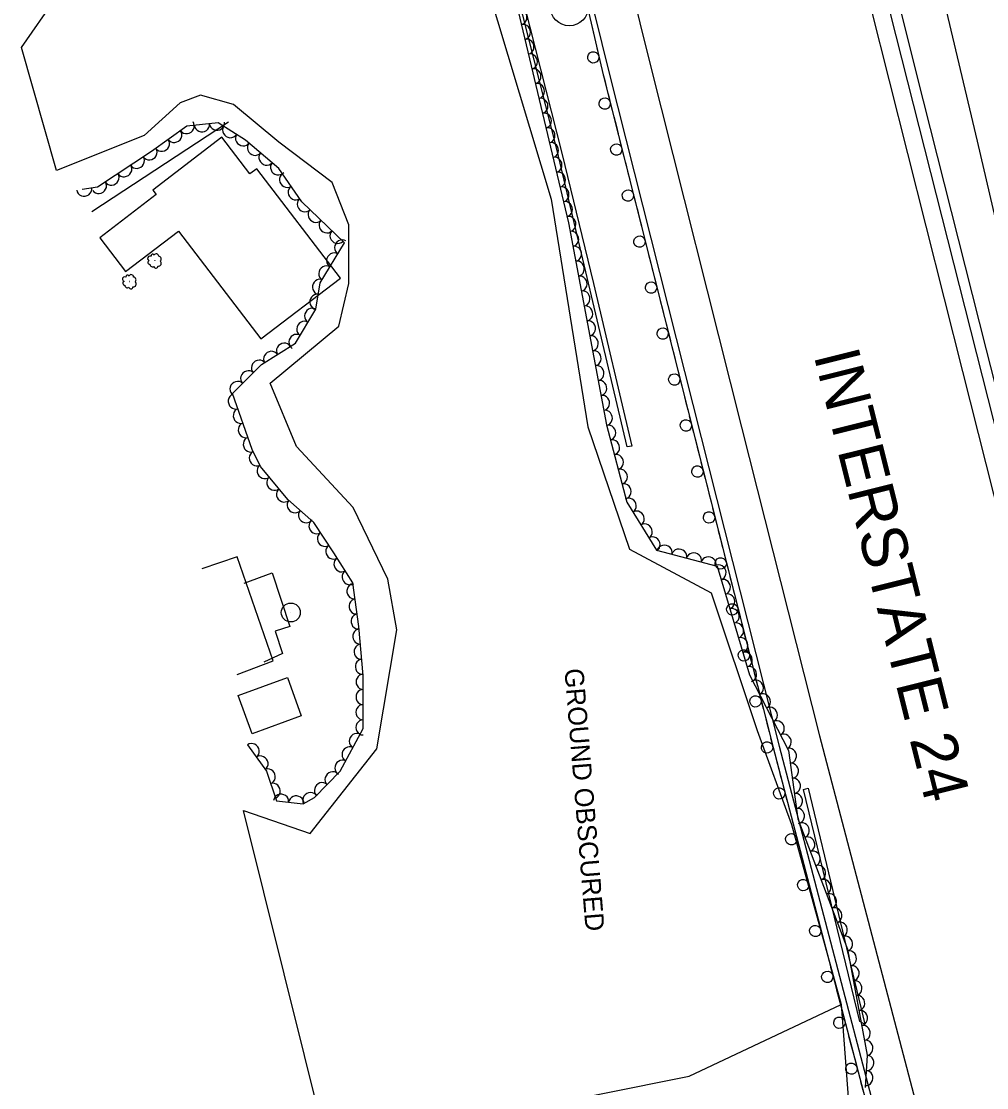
# Model space of a CAD drawing. Extents: x 1746719 to 1766531, y 631721 to 662391.
# Drawn here: x 1753677.7 to 1753932, y 651183.8 to 651464.9 of the extents above; entities that cross this region are included whole.
import ezdxf

# ---------------------------------------------------------------- set-up
doc = ezdxf.new("R2010")
doc.units = 0
for name, color, linetype in [('SURVEY - AERIAL SURVEY - Photo Control - Points - Elevations', 7, 'Continuous'), ('SURVEY - AERIAL SURVEY - Photo Control - Points - Locators', 7, 'Continuous'), ('SURVEY - AERIAL SURVEY - Photo Control - Points - Numbers', 7, 'Continuous'), ('SURVEY - AERIAL SURVEY - Photo Control with Text', 7, 'Continuous'), ('SURVEY - CENTERLINE - Existing Roads Curve Text', 7, 'Continuous'), ('SURVEY - CONTROL - Grid', 7, 'Continuous'), ('SURVEY - CONTROL - Points - Numbers', 7, 'Continuous')]:
    doc.layers.add(name, color=color, linetype=linetype)

msp = doc.modelspace()

# ---------------------------------------------------------------- linework, layer by layer
at = {"layer": 'SURVEY - AERIAL SURVEY - Photo Control - Points - Elevations'}
for points in [[(1753816.84, 651890.61), (1753830.85, 651831.07), (1753849.61, 651754.68), (1753866.95, 651686.19), (1753887.01, 651606.61), (1753909.25, 651518.98), (1753929.48, 651433.33), (1753948.74, 651350.66), (1753973.86, 651243.1), (1753985.66, 651193.84)], [(1753794.98, 651884.53), (1753806.82, 651840.15), (1753821.01, 651784.89), (1753834.83, 651732.27), (1753860.34, 651631.97), (1753880.16, 651554.64), (1753901.48, 651468.39), (1753925.64, 651372.59), (1753946.08, 651291.56), (1753972.17, 651192.06)], [(1753733.96, 651866.94), (1753776.74, 651717.25), (1753802.2, 651617.13), (1753821.97, 651539.99), (1753843.26, 651453.86), (1753867.46, 651357.92), (1753887.97, 651276.61), (1753914.13, 651176.84)], [(1753723.39, 651863.92), (1753766.12, 651714.38), (1753791.54, 651614.41), (1753811.31, 651537.31), (1753832.59, 651451.19), (1753856.8, 651355.23), (1753877.32, 651273.87), (1753903.49, 651174.05)]]:
    msp.add_lwpolyline(points, dxfattribs=at)
at = {"layer": 'SURVEY - AERIAL SURVEY - Photo Control - Points - Locators'}
for points in [[(1753736.22, 651256.87), (1753753.86, 651250.84), (1753771.37, 651273.18), (1753776.68, 651304.52), (1753774.32, 651317.9), (1753765.17, 651336.78), (1753750.18, 651352.85), (1753743.25, 651369.51), (1753761.37, 651384.52), (1753763.97, 651395.81), (1753763.96, 651411.24), (1753759.65, 651422.43), (1753745.55, 651433.05), (1753733.61, 651442.94), (1753724.93, 651445.41), (1753719.55, 651443.38), (1753710.13, 651434.8), (1753687.03, 651425.53), (1753677.74, 651457.95), (1753695.84, 651484.06)], [(1753797.48, 651484.03), (1753817.32, 651418.04), (1753826.96, 651357.98), (1753837.9, 651325.75), (1753859.48, 651314.29), (1753871.54, 651277.94), (1753880.62, 651253.22), (1753893.68, 651205.75), (1753895.74, 651178.95)], [(1753763.07, 651149.28), (1753736.22, 651256.87)], [(1753806.88, 651177.52), (1753853.69, 651186.9), (1753893.68, 651205.75), (1753895.74, 651178.95)]]:
    msp.add_lwpolyline(points, dxfattribs=at)
at = {"layer": 'SURVEY - AERIAL SURVEY - Photo Control - Points - Numbers'}
for points in [[(1753799.94, 651885.56), (1753810.5, 651844.2), (1753821.9, 651799.8), (1753839.06, 651731.78), (1753855.62, 651667.72), (1753872.26, 651603.05), (1753890.45, 651531.05), (1753906.57, 651466.95), (1753932.35, 651365.49), (1753954.46, 651278.36), (1753976.4, 651192.62)], [(1753803.22, 651885.31), (1753820.95, 651816.44), (1753833.87, 651765.85), (1753848.12, 651709.37), (1753866.6, 651636.42), (1753879.49, 651585.73), (1753898.23, 651511.96), (1753915.25, 651443.91), (1753931.92, 651378.33), (1753946.18, 651322.21), (1753967.15, 651242.27), (1753979.08, 651193.03)], [(1753703.75, 651873.05), (1753717.54, 651820.22), (1753736.79, 651745.77), (1753755.12, 651677.96), (1753771.54, 651615.12), (1753790.61, 651546.41), (1753820.14, 651430.11), (1753828.48, 651395.77), (1753838.52, 651352.89), (1753837.34, 651352.78), (1753818.9, 651430.81), (1753796.23, 651520.29), (1753782.9, 651570.04), (1753766.88, 651627.82), (1753754.29, 651677.05), (1753741.7, 651724.51), (1753730.14, 651767.33), (1753713.81, 651831.32), (1753702.74, 651872.76)], [(1753827.21, 651466.99), (1753831.02, 651450.8), (1753855.22, 651354.83), (1753875.75, 651273.47), (1753901.92, 651173.64)], [(1753827.9, 651464.06), (1753828.44, 651461.77)], [(1753828.44, 651461.77), (1753828.98, 651459.49)], [(1753829.34, 651457.93), (1753830.4, 651453.45)], [(1753830.76, 651451.89), (1753831.02, 651450.8), (1753831.32, 651449.61)], [(1753831.32, 651449.61), (1753831.89, 651447.33)], [(1753832.28, 651445.78), (1753833.41, 651441.32)], [(1753833.8, 651439.77), (1753834.38, 651437.49)], [(1753834.38, 651437.49), (1753834.95, 651435.21)], [(1753835.34, 651433.66), (1753836.47, 651429.2)], [(1753836.86, 651427.65), (1753837.43, 651425.37)], [(1753837.43, 651425.37), (1753838.01, 651423.09)], [(1753838.4, 651421.54), (1753839.52, 651417.08)], [(1753839.91, 651415.53), (1753840.49, 651413.25)], [(1753840.49, 651413.25), (1753841.06, 651410.97)], [(1753841.46, 651409.42), (1753842.58, 651404.96)], [(1753842.97, 651403.41), (1753843.55, 651401.13)], [(1753843.55, 651401.13), (1753844.12, 651398.85)], [(1753844.51, 651397.3), (1753845.64, 651392.84)], [(1753846.03, 651391.29), (1753846.6, 651389.01)], [(1753846.6, 651389.01), (1753847.18, 651386.73)], [(1753847.57, 651385.18), (1753848.69, 651380.72)], [(1753849.08, 651379.17), (1753849.66, 651376.89)], [(1753849.66, 651376.89), (1753850.23, 651374.61)], [(1753850.63, 651373.06), (1753851.75, 651368.6)], [(1753852.14, 651367.05), (1753852.72, 651364.77)], [(1753852.72, 651364.77), (1753853.29, 651362.49)], [(1753853.68, 651360.94), (1753854.81, 651356.48)], [(1753855.2, 651354.92), (1753855.22, 651354.83), (1753855.77, 651352.65)], [(1753855.77, 651352.65), (1753856.35, 651350.37)], [(1753856.74, 651348.82), (1753857.86, 651344.36)], [(1753858.26, 651342.8), (1753858.83, 651340.53)], [(1753858.83, 651340.53), (1753859.41, 651338.25)], [(1753859.8, 651336.7), (1753860.92, 651332.23)], [(1753861.31, 651330.68), (1753861.89, 651328.41)], [(1753861.89, 651328.41), (1753862.46, 651326.13)], [(1753862.85, 651324.58), (1753863.98, 651320.11)], [(1753864.37, 651318.56), (1753864.95, 651316.29)], [(1753864.95, 651316.29), (1753865.52, 651314.01)], [(1753865.91, 651312.45), (1753867.04, 651307.99)], [(1753867.43, 651306.44), (1753868, 651304.17)], [(1753868, 651304.17), (1753868.58, 651301.89)], [(1753868.97, 651300.33), (1753870.09, 651295.87)], [(1753870.49, 651294.32), (1753871.06, 651292.04)], [(1753871.06, 651292.04), (1753871.64, 651289.77)], [(1753872.03, 651288.21), (1753873.15, 651283.75)], [(1753873.54, 651282.2), (1753874.12, 651279.92)], [(1753874.12, 651279.92), (1753874.69, 651277.65)], [(1753875.08, 651276.09), (1753875.75, 651273.47), (1753876.23, 651271.64)], [(1753876.63, 651270.09), (1753877.23, 651267.82)], [(1753877.23, 651267.82), (1753877.82, 651265.54)], [(1753878.23, 651264), (1753879.4, 651259.55)], [(1753883.75, 651262.44), (1753884.97, 651262.74), (1753899.92, 651200.62), (1753898.62, 651201.32), (1753883.75, 651262.44)], [(1753879.8, 651258), (1753880.4, 651255.73)], [(1753880.4, 651255.73), (1753880.99, 651253.45)], [(1753881.4, 651251.91), (1753882.57, 651247.45)], [(1753882.97, 651245.91), (1753883.57, 651243.63)], [(1753883.57, 651243.63), (1753884.16, 651241.36)], [(1753884.57, 651239.81), (1753885.74, 651235.36)], [(1753886.14, 651233.82), (1753886.74, 651231.54)], [(1753886.74, 651231.54), (1753887.33, 651229.27)], [(1753887.74, 651227.72), (1753888.91, 651223.27)], [(1753889.31, 651221.72), (1753889.91, 651219.45)], [(1753889.91, 651219.45), (1753890.5, 651217.18)], [(1753890.91, 651215.63), (1753892.08, 651211.18)], [(1753892.48, 651209.63), (1753893.08, 651207.36)], [(1753893.08, 651207.36), (1753893.67, 651205.09)], [(1753894.08, 651203.54), (1753895.25, 651199.09)], [(1753895.65, 651197.54), (1753896.25, 651195.27)], [(1753896.25, 651195.27), (1753896.84, 651193)], [(1753897.25, 651191.45), (1753898.42, 651187)], [(1753898.82, 651185.45), (1753899.42, 651183.18)]]:
    msp.add_lwpolyline(points, dxfattribs=at)
for centre, start, end in [((1753828.4, 651455.37), 126.4794, 126.4696), ((1753831.39, 651443.2), 127.4165, 127.4067), ((1753834.44, 651431.08), 127.4165, 127.4067), ((1753837.5, 651418.96), 127.4165, 127.4067), ((1753840.56, 651406.84), 127.4165, 127.4067), ((1753843.61, 651394.72), 127.4165, 127.4067), ((1753846.67, 651382.6), 127.4165, 127.4067), ((1753849.73, 651370.48), 127.4165, 127.4067), ((1753852.79, 651358.36), 127.4165, 127.4067), ((1753855.84, 651346.24), 127.4182, 127.4084), ((1753858.9, 651334.12), 127.4182, 127.4084), ((1753861.96, 651322), 127.4182, 127.4084), ((1753865.01, 651309.88), 127.4182, 127.4084), ((1753868.07, 651297.76), 127.4182, 127.4084), ((1753871.13, 651285.64), 127.4182, 127.4084), ((1753874.19, 651273.52), 127.4182, 127.4084), ((1753877.36, 651261.41), 127.9515, 127.9417), ((1753880.53, 651249.32), 127.9515, 127.9417), ((1753883.7, 651237.23), 127.9515, 127.9417), ((1753886.87, 651225.14), 127.9515, 127.9417), ((1753890.04, 651213.05), 127.9515, 127.9417), ((1753893.21, 651200.96), 127.9515, 127.9417), ((1753896.38, 651188.86), 127.9515, 127.9417)]:
    msp.add_arc(centre, 1.5, start, end, dxfattribs=at)
at = {"layer": 'SURVEY - AERIAL SURVEY - Photo Control with Text'}
for points in [[(1753699.75, 651873.5), (1753708.69, 651845.05), (1753721.94, 651788.69), (1753733.46, 651743.77), (1753745.26, 651698.47), (1753758.47, 651650.75), (1753769.58, 651611.97), (1753785.51, 651554.44), (1753799.95, 651501.83), (1753807.33, 651473.18), (1753821.86, 651411.8), (1753831.88, 651358.5), (1753837.25, 651338.18), (1753845.02, 651325.52), (1753860.99, 651321.27), (1753869.58, 651292.66), (1753879.85, 651272.68), (1753882.25, 651254.73), (1753895.38, 651220.36), (1753900.55, 651192.39), (1753899.98, 651183.91)], [(1753737.35, 651274.21), (1753742.29, 651267.26), (1753744.94, 651259.45), (1753751.95, 651258.67), (1753754.98, 651260.36), (1753761.75, 651267.3), (1753767.77, 651278.49), (1753767.79, 651292.49), (1753766.68, 651305.36), (1753765.06, 651316.94), (1753760.01, 651324.83), (1753754.74, 651332.79), (1753747.94, 651338.85), (1753740.7, 651347.59), (1753738.54, 651352.04), (1753733.39, 651366.82), (1753741.03, 651374.41), (1753749.94, 651380.07), (1753755.3, 651389.02), (1753756.47, 651395.98), (1753762.87, 651406.46), (1753751.6, 651417.33), (1753745.57, 651426.1), (1753736.77, 651433.56), (1753729.59, 651438.09), (1753721.36, 651437.21), (1753712.03, 651430.59), (1753697.8, 651421.14), (1753693.79, 651420.6)]]:
    msp.add_lwpolyline(points, dxfattribs=at)
for centre in [(1753712.88, 651401.79), (1753706.26, 651396.3)]:
    msp.add_circle(centre, 0.022, dxfattribs=at)
for centre, radius, start, end in [((1753711.6, 651402.4), 0.629, 60.6531, 254.0728), ((1753712.32, 651403.09), 0.433, 20.6325, 199.3781), ((1753713.3, 651402.98), 0.631, 358.5163, 155.3052), ((1753713.87, 651402.25), 0.719, 307.569, 85.0933), ((1753711.54, 651401.33), 0.479, 103.2718, 280.591), ((1753712.3, 651400.84), 0.679, 178.5589, 305.4045), ((1753713.22, 651400.37), 0.527, 188.7178, 3.718), ((1753713.89, 651401.1), 0.714, 258.4649, 54.3034), ((1753704.99, 651396.91), 0.629, 60.6531, 254.0728), ((1753705.7, 651397.6), 0.433, 20.6325, 199.3781), ((1753706.68, 651397.49), 0.631, 358.5163, 155.3052), ((1753707.25, 651396.76), 0.719, 307.569, 85.0933), ((1753704.92, 651395.84), 0.479, 103.2718, 280.591), ((1753705.69, 651395.35), 0.679, 178.5589, 305.4045), ((1753706.6, 651394.88), 0.527, 188.7178, 3.718), ((1753707.27, 651395.61), 0.714, 258.4649, 54.3034)]:
    msp.add_arc(centre, radius, start, end, dxfattribs=at)
for centre, major_axis in [((1753809.04, 651465.97), (0.46, -1.95)), ((1753809.96, 651462.08), (0.46, -1.95)), ((1753810.88, 651458.18), (0.46, -1.95)), ((1753811.8, 651454.29), (0.46, -1.95)), ((1753812.72, 651450.4), (0.46, -1.95)), ((1753813.64, 651446.51), (0.46, -1.95)), ((1753814.57, 651442.61), (0.46, -1.95)), ((1753815.49, 651438.72), (0.46, -1.95)), ((1753721.34, 651437.19), (-1.63, -1.16)), ((1753725.31, 651437.63), (-1.99, -0.21)), ((1753729.29, 651438.06), (-1.99, -0.21)), ((1753732.71, 651436.12), (-1.69, 1.07)), ((1753816.41, 651434.83), (0.46, -1.95)), ((1753718.07, 651434.87), (-1.63, -1.16)), ((1753736.1, 651433.98), (-1.69, 1.07)), ((1753711.54, 651430.26), (-1.67, -1.11)), ((1753714.81, 651432.56), (-1.63, -1.16)), ((1753739.22, 651431.49), (-1.53, 1.29)), ((1753817.33, 651430.94), (0.46, -1.95)), ((1753708.21, 651428.05), (-1.67, -1.11)), ((1753742.27, 651428.9), (-1.53, 1.29)), ((1753818.25, 651427.05), (0.46, -1.95)), ((1753704.88, 651425.83), (-1.67, -1.11)), ((1753745.32, 651426.31), (-1.53, 1.29)), ((1753701.54, 651423.62), (-1.67, -1.11)), ((1753747.65, 651423.08), (-1.13, 1.65)), ((1753819.17, 651423.15), (0.46, -1.95)), ((1753694.32, 651420.67), (-1.98, -0.27)), ((1753698.21, 651421.41), (-1.67, -1.11)), ((1753749.92, 651419.78), (-1.13, 1.65)), ((1753820.1, 651419.26), (0.46, -1.95)), ((1753752.34, 651416.62), (-1.44, 1.39)), ((1753821.02, 651415.37), (0.46, -1.95)), ((1753755.22, 651413.84), (-1.44, 1.39)), ((1753758.1, 651411.06), (-1.44, 1.39)), ((1753821.92, 651411.47), (0.37, -1.97)), ((1753760.98, 651408.28), (-1.44, 1.39)), ((1753822.66, 651407.54), (0.37, -1.97)), ((1753762.16, 651405.29), (1.04, 1.71)), ((1753823.4, 651403.61), (0.37, -1.97)), ((1753760.07, 651401.88), (1.04, 1.71)), ((1753757.99, 651398.46), (1.04, 1.71)), ((1753824.14, 651399.68), (0.37, -1.97)), ((1753824.88, 651395.75), (0.37, -1.97)), ((1753756.29, 651394.9), (0.33, 1.97)), ((1753755.62, 651390.96), (0.33, 1.97)), ((1753825.62, 651391.82), (0.37, -1.97)), ((1753754.25, 651387.28), (1.03, 1.72)), ((1753826.36, 651387.88), (0.37, -1.97)), ((1753752.2, 651383.85), (1.03, 1.72)), ((1753827.09, 651383.95), (0.37, -1.97)), ((1753750.14, 651380.41), (1.03, 1.72)), ((1753827.83, 651380.02), (0.37, -1.97)), ((1753743.52, 651376), (1.69, 1.07)), ((1753746.9, 651378.14), (1.69, 1.07)), ((1753828.57, 651376.09), (0.37, -1.97)), ((1753740.28, 651373.67), (1.42, 1.41)), ((1753737.45, 651370.85), (1.42, 1.41)), ((1753829.31, 651372.16), (0.37, -1.97)), ((1753734.61, 651368.04), (1.42, 1.41)), ((1753830.05, 651368.23), (0.37, -1.97)), ((1753734.13, 651364.67), (-0.66, 1.89)), ((1753830.79, 651364.3), (0.37, -1.97)), ((1753735.45, 651360.89), (-0.66, 1.89)), ((1753831.53, 651360.37), (0.37, -1.97)), ((1753736.77, 651357.12), (-0.66, 1.89)), ((1753832.41, 651356.47), (0.51, -1.93)), ((1753738.09, 651353.34), (-0.66, 1.89)), ((1753833.44, 651352.6), (0.51, -1.93)), ((1753739.69, 651349.68), (-0.87, 1.8)), ((1753834.46, 651348.73), (0.51, -1.93)), ((1753741.77, 651346.3), (-1.28, 1.54)), ((1753835.48, 651344.87), (0.51, -1.93)), ((1753744.32, 651343.22), (-1.28, 1.54)), ((1753746.88, 651340.14), (-1.28, 1.54)), ((1753836.5, 651341), (0.51, -1.93)), ((1753749.68, 651337.3), (-1.49, 1.33)), ((1753837.81, 651337.26), (1.05, -1.7)), ((1753752.66, 651334.64), (-1.49, 1.33)), ((1753839.91, 651333.85), (1.05, -1.7)), ((1753755.41, 651331.77), (-1.1, 1.67)), ((1753842, 651330.44), (1.05, -1.7)), ((1753757.62, 651328.44), (-1.1, 1.67)), ((1753844.09, 651327.03), (1.05, -1.7)), ((1753847.17, 651324.94), (1.93, -0.51)), ((1753759.83, 651325.1), (-1.1, 1.67)), ((1753851.03, 651323.91), (1.93, -0.51)), ((1753854.9, 651322.89), (1.93, -0.51)), ((1753761.99, 651321.74), (-1.08, 1.68)), ((1753858.76, 651321.86), (1.93, -0.51)), ((1753861.48, 651319.64), (0.57, -1.92)), ((1753764.15, 651318.37), (-1.08, 1.68)), ((1753765.38, 651314.66), (-0.28, 1.98)), ((1753862.63, 651315.81), (0.57, -1.92)), ((1753863.78, 651311.98), (0.57, -1.92)), ((1753765.93, 651310.7), (-0.28, 1.98)), ((1753864.93, 651308.15), (0.57, -1.92)), ((1753766.48, 651306.73), (-0.28, 1.98)), ((1753766.9, 651302.76), (-0.17, 1.99)), ((1753866.08, 651304.32), (0.57, -1.92)), ((1753867.23, 651300.49), (0.57, -1.92)), ((1753767.25, 651298.77), (-0.17, 1.99)), ((1753767.59, 651294.79), (-0.17, 1.99)), ((1753868.38, 651296.66), (0.57, -1.92)), ((1753869.53, 651292.83), (0.57, -1.92)), ((1753767.79, 651290.8), (0, 2)), ((1753871.33, 651289.26), (0.91, -1.78)), ((1753767.78, 651286.8), (0, 2)), ((1753873.16, 651285.7), (0.91, -1.78)), ((1753767.77, 651282.8), (0, 2)), ((1753874.99, 651282.14), (0.91, -1.78)), ((1753767.77, 651278.8), (0, 2)), ((1753876.81, 651278.58), (0.91, -1.78)), ((1753766.02, 651275.24), (0.95, 1.76)), ((1753878.64, 651275.03), (0.91, -1.78)), ((1753738.51, 651272.58), (1.16, -1.63)), ((1753764.12, 651271.71), (0.95, 1.76)), ((1753740.82, 651269.32), (1.16, -1.63)), ((1753880.03, 651271.33), (0.27, -1.98)), ((1753742.76, 651265.86), (0.64, -1.89)), ((1753762.23, 651268.19), (0.95, 1.76)), ((1753880.56, 651267.36), (0.27, -1.98)), ((1753759.66, 651265.16), (1.4, 1.43)), ((1753881.09, 651263.4), (0.27, -1.98)), ((1753744.05, 651262.08), (0.64, -1.89)), ((1753756.87, 651262.3), (1.4, 1.43)), ((1753746.16, 651259.31), (1.99, -0.22)), ((1753750.14, 651258.87), (1.99, -0.22)), ((1753753.85, 651259.73), (1.75, 0.98)), ((1753881.62, 651259.44), (0.27, -1.98)), ((1753882.15, 651255.47), (0.27, -1.98)), ((1753883.41, 651251.69), (0.71, -1.87)), ((1753884.84, 651247.95), (0.71, -1.87)), ((1753886.27, 651244.22), (0.71, -1.87)), ((1753887.69, 651240.48), (0.71, -1.87)), ((1753889.12, 651236.74), (0.71, -1.87)), ((1753890.55, 651233.01), (0.71, -1.87)), ((1753891.98, 651229.27), (0.71, -1.87)), ((1753893.4, 651225.53), (0.71, -1.87)), ((1753894.83, 651221.8), (0.71, -1.87)), ((1753895.83, 651217.94), (0.36, -1.97)), ((1753896.55, 651214.01), (0.36, -1.97)), ((1753897.28, 651210.07), (0.36, -1.97)), ((1753898.01, 651206.14), (0.36, -1.97)), ((1753898.73, 651202.21), (0.36, -1.97)), ((1753899.46, 651198.27), (0.36, -1.97)), ((1753900.19, 651194.34), (0.36, -1.97)), ((1753900.41, 651190.38), (-0.13, -2)), ((1753900.15, 651186.39), (-0.13, -2))]:
    msp.add_ellipse(centre, major_axis=major_axis, ratio=0.940188, start_param=0, end_param=3.141593, dxfattribs=at)
at = {"layer": 'SURVEY - CENTERLINE - Existing Roads Curve Text'}
msp.add_line((1753748.72, 651309.06), (1753748.72, 651309.06), dxfattribs=at)
for points in [[(1753732.3, 651438.26), (1753696.34, 651414.7)], [(1753732.3, 651438.26), (1753696.34, 651414.7)], [(1753734.57, 651292.76), (1753744.09, 651296.35), (1753734.6, 651323.75), (1753725.24, 651320.56)], [(1753736.43, 651316.85), (1753743.77, 651319.51), (1753748.49, 651305.37), (1753744.61, 651304.15), (1753746.49, 651298.26), (1753741.6, 651295.96)]]:
    msp.add_lwpolyline(points, dxfattribs=at)
for points in [[(1753761.78, 651397.23), (1753739.74, 651426.02), (1753737.96, 651424.66), (1753730.56, 651434.33), (1753712.37, 651420.41), (1753713.29, 651419.21), (1753698.39, 651407.8), (1753705.2, 651398.91), (1753719.13, 651409.58), (1753740.84, 651381.21)], [(1753734.84, 651287.23), (1753747.81, 651291.93), (1753751.47, 651281.84), (1753738.5, 651277.13)]]:
    msp.add_lwpolyline(points, close=True, dxfattribs=at)
msp.add_circle((1753748.72, 651309.08), 2.5, dxfattribs=at)
at = {"layer": 'SURVEY - CONTROL - Grid'}
msp.add_circle((1753822.08, 651468.7), 5, dxfattribs=at)

# ---------------------------------------------------------------- texts
at = {"layer": 'SURVEY - AERIAL SURVEY - Photo Control - Points - Locators'}
msp.add_text('GROUND OBSCURED', height=5, rotation=274.6437, dxfattribs=at).set_placement((1753820.78, 651294.15))
at = {"layer": 'SURVEY - CONTROL - Points - Numbers'}
msp.add_text('INTERSTATE 24', height=12, rotation=284.0221, dxfattribs=at).set_placement((1753886.4, 651376.92))

doc.saveas('drawing.dxf')
